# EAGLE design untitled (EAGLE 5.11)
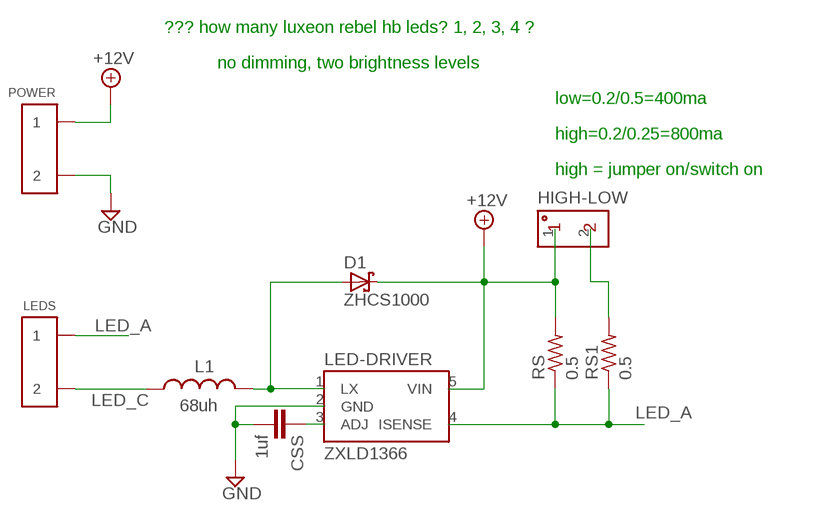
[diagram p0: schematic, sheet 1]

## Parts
CSS  1uf  C-EUC0805  [C0805]
D1  ZHCS1000  BAS40  [SOT23]
HIGH-LOW  HEADER-2SMD  [HEADER-POWER-SMD]
L1  68uh  INDUCTOR3131  [SMD3131]
LED-DRIVER  ZXLD1366  [TSOT23-5]
LEDS  SCREW-CLAMP-2908  [SCREW-CLAMP-PUSHIN-2-2.5MM]
POWER  SCREW-CLAMP-2908  [SCREW-CLAMP-PUSHIN-2-2.5MM]
RS  0.5  R-US_M1206  [M1206]
RS1  0.5  R-US_M1206  [M1206]

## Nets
+12V: D1.3(C) HIGH-LOW.1 LED-DRIVER.5(VIN) POWER.1 RS.2
GND: CSS.2 LED-DRIVER.2(GND) POWER.2
LED_A: LED-DRIVER.4(ISENSE) LEDS.1 RS1.1 RS.1
LED_C: L1.1 LEDS.2
N$1: HIGH-LOW.2 RS1.2
N$5: CSS.1 LED-DRIVER.3(ADJ)
N$6: D1.1(A) L1.2 LED-DRIVER.1(LX)

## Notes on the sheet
- ??? how many luxeon rebel hb leds? 1, 2, 3, 4 ?
- no dimming, two brightness levels
- low=0.2/0.5=400ma
- high=0.2/0.25=800ma
- high = jumper on/switch on

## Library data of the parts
CSS = rcl:C-EU: CAPACITOR, European symbol
D1 = diode:BAS40: Silicon Schottky Diodes
HIGH-LOW = trl:HEADER-2
L1 = trl:INDUCTOR
LED-DRIVER = trl:ZXLD1366
LEDS POWER = trl:SCREW-CLAMP-2
RS RS1 = resistor:R-US_: RESISTOR, American symbol

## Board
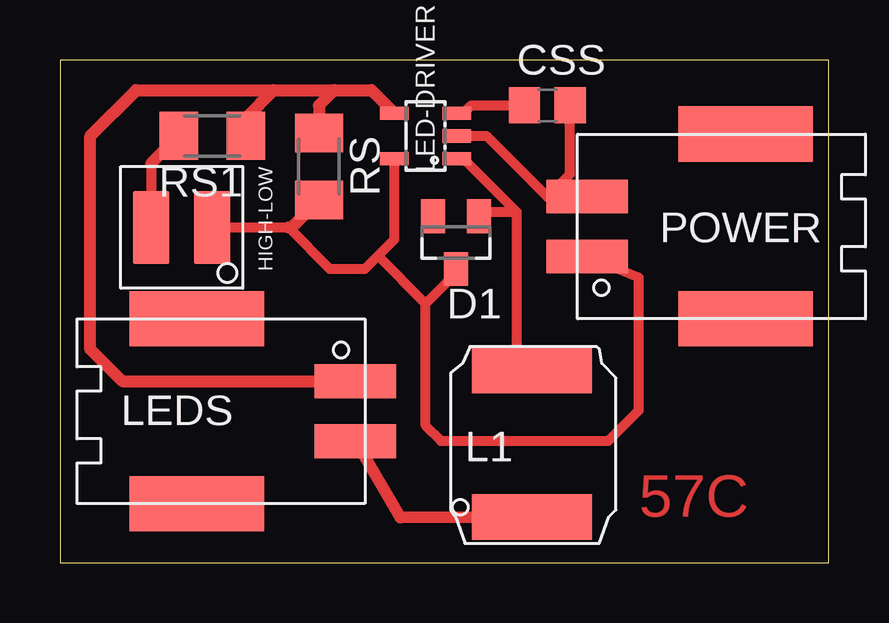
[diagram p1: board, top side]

Size 32.05 x 20.95 mm. Coordinates in mm from the lower left corner, seen from the top.
Outline: 0,0 32.05,0 32.05,20.95 0,20.95 0,0
Copper layers (1*16): Top 0.035mm / dielectric 1.5mm / Bottom 0.035mm
Design rules "default": minimum track width 10mil, minimum drill 0.6mm, track to track 8mil, track to pad 8mil, pad to pad 8mil, via to via 8mil, smd to smd 8mil, copper to edge 40mil, drill to drill 8mil, minimum pad ring 10mil, minimum via ring 8mil, stop-mask expansion 4mil, vias tented up to drill 0mil, thermal gap 10mil

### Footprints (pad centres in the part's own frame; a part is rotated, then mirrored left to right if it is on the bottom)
C0805 = smd 1.3 x 1.5: 1 -0.95,0; 2 0.95,0
SOT23 = smd 1 x 1.4: 1 -0.95,-1.1; 2 0.95,-1.1; 3 0,1.1
HEADER-POWER-SMD = smd 3.048 x 1.524: 1 0,1.27; 2 0,-1.27
SMD3131 = smd 5 x 1.9: 1 0,0; 2 0,6.1
TSOT23-5 = smd 0.55 x 1.2: 1 -0.95,-1.3; 2 0,-1.3; 3 0.95,-1.3; 4 0.95,1.3; 5 -0.95,1.3
SCREW-CLAMP-PUSHIN-2-2.5MM = smd 1.4 x 3.4: 1 -1.21,5.33; 2 1.29,5.33 | smd 2.3 x 5.6: 11 -3.81,-1.27; 22 3.89,-1.27
M1206 = smd 1.6 x 2: 1 -1.4,0; 2 1.4,0

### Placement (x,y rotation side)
CSS  20.32,19.05 0 top
D1  16.51,13.34 180 top
HIGH-LOW  5.08,13.97 270 top
L1  19.68,1.91 0 top
LED-DRIVER  15.24,17.78 90 top
LEDS  6.99,6.35 270 top
POWER  27.3,13.97 90 top
RS  10.79,16.51 270 top
RS1  6.35,17.78 180 top

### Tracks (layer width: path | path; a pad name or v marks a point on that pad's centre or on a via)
+12V
  Top 0.406: LED-DRIVER.5 13.94,13.47 13.25,12.79 | 13.25,12.79 12.7,12.23 11.26,12.23 9.53,13.97 HIGH-LOW.1 | POWER.1 24.13,11.88 24.13,6.35 22.86,5.08 15.88,5.08 15.24,5.71 15.24,10.79 | 15.24,10.79 13.25,12.79 | D1.3 16.51,12.06 15.24,10.79
  Top 0.508: 9.53,13.97 9.65,13.97 RS.2
GND
  Top 0.406: LED-DRIVER.2 17.78,17.78 20.32,15.24 | 20.32,15.24 21.95,15.24 POWER.2 | CSS.2 21.27,16.19 20.32,15.24
LED_A
  Top 0.406: RS.1 10.66,17.78 | 7.62,17.91 RS1.1 7.75,18.55
  Top 0.508: LEDS.1 2.6,7.56 1.27,8.89 1.27,17.78 3.17,19.68 8.89,19.68 | 8.89,19.68 11.43,19.68 | 11.43,19.68 12.98,19.68 LED-DRIVER.4 | RS.1 10.79,19.05 11.43,19.68 | 8.89,19.68 7.75,18.55
LED_C
  Top 0.508: LEDS.2 14.18,1.89 L1.1
N$1
  Top 0.406: 3.81,16.64 HIGH-LOW.2
  Top 0.508: 3.81,16.64 RS1.2
N$5
  Top 0.406: LED-DRIVER.3 16.82,18.73 17.14,19.05 CSS.1
N$6
  Top 0.406: LED-DRIVER.1 16.82,16.83 19.05,14.61 | 19.05,14.61 19.05,8.64 L1.2 | 19.05,14.61 17.63,14.61 D1.1

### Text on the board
Top: 57C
